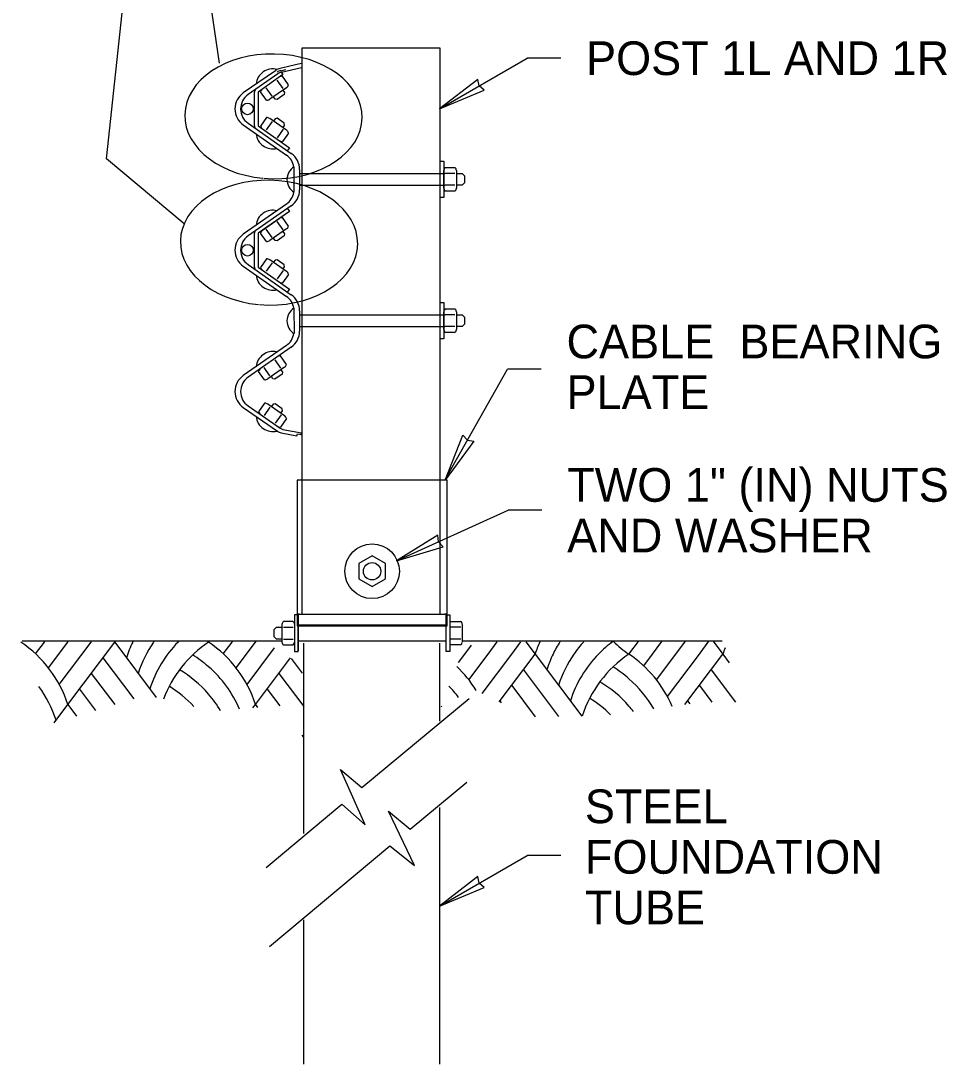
# Model space of a CAD drawing. Extents: x 1312564.2 to 1312581.5, y 1207298.4 to 1207352.6.
# Drawn here: x 1312572.439 to 1312574.64, y 1207329.716 to 1207332.195 of the extents above; entities that cross this region are included whole.
import ezdxf

# ---------------------------------------------------------------- set-up
doc = ezdxf.new("R2010")
doc.units = 0
for name, color, linetype in [('Level 15', 7, 'Continuous'), ('Level 16', 7, 'Continuous'), ('Level 20', 7, 'Continuous'), ('Level 3', 7, 'Continuous'), ('Level 6', 7, 'Continuous')]:
    doc.layers.add(name, color=color, linetype=linetype)

msp = doc.modelspace()

# ---------------------------------------------------------------- linework, layer by layer
at = {"layer": 'Level 15'}
for p, q in [((1312572.9113, 1207332.094), (1312572.7708, 1207333.0638)), ((1312573.4336, 1207331.9858), (1312573.6419, 1207332.1061)), ((1312573.722, 1207332.1061), (1312573.6419, 1207332.1061)), ((1312573.4469, 1207331.1033), (1312573.5956, 1207331.3671)), ((1312573.6757, 1207331.3671), (1312573.5956, 1207331.3671)), ((1312573.3321, 1207330.9118), (1312573.5972, 1207331.032)), ((1312573.6773, 1207331.032), (1312573.5972, 1207331.032)), ((1312573.4336, 1207330.0915), (1312573.6419, 1207330.2118)), ((1312573.722, 1207330.2118), (1312573.6419, 1207330.2118))]:
    msp.add_line(p, q, dxfattribs=at)
for points in [[(1312572.8272, 1207331.7124), (1312572.6428, 1207331.8673), (1312572.7708, 1207333.0638)], [(1312573.0218, 1207330.1827), (1312573.2017, 1207330.3332), (1312573.2574, 1207330.2842), (1312573.1987, 1207330.4157), (1312573.2496, 1207330.3731), (1312573.5046, 1207330.5844)], [(1312573.03, 1207329.9954), (1312573.3162, 1207330.2346), (1312573.3742, 1207330.1882), (1312573.3131, 1207330.3171), (1312573.364, 1207330.2745), (1312573.4986, 1207330.3861)]]:
    msp.add_lwpolyline(points, dxfattribs=at)
for points in [[(1312573.4336, 1207331.9858), (1312573.54, 1207332.03), (1312573.528, 1207332.0403), (1312573.5251, 1207332.0559)], [(1312573.4474, 1207331.1033), (1312573.4896, 1207331.2105), (1312573.5001, 1207331.1987), (1312573.5157, 1207331.1961)], [(1312573.3321, 1207330.9118), (1312573.4424, 1207330.9454), (1312573.4314, 1207330.9568), (1312573.43, 1207330.9726)], [(1312573.4336, 1207330.0915), (1312573.54, 1207330.1357), (1312573.528, 1207330.146), (1312573.5251, 1207330.1616)]]:
    msp.add_lwpolyline(points, close=True, dxfattribs=at)
for centre in [(1312573.0394, 1207331.9679), (1312573.0289, 1207331.6678)]:
    msp.add_ellipse(centre, major_axis=(0.2106, -0.004), ratio=0.703427, start_param=4.618435, end_param=10.890865, dxfattribs=at)
at = {"layer": 'Level 16'}
for p, q in [((1312573.0439, 1207332.0765), (1312572.9677, 1207332.0236)), ((1312573.1063, 1207332.0832), (1312573.0585, 1207332.0725)), ((1312573.0501, 1207332.069), (1312572.9791, 1207332.0196)), ((1312572.979, 1207331.9515), (1312573.0818, 1207331.8797)), ((1312572.9677, 1207331.9478), (1312573.0704, 1207331.8761)), ((1312573.0881, 1207331.848), (1312573.0881, 1207331.7875)), ((1312573.1015, 1207331.8419), (1312573.1015, 1207331.7934)), ((1312573.0704, 1207331.7595), (1312572.9677, 1207331.6877)), ((1312573.0818, 1207331.7555), (1312572.979, 1207331.6838)), ((1312572.9677, 1207331.612), (1312573.0704, 1207331.5402)), ((1312572.979, 1207331.6157), (1312573.0818, 1207331.5439)), ((1312573.0878, 1207331.5118), (1312573.0883, 1207331.4518)), ((1312573.1015, 1207331.506), (1312573.1015, 1207331.4576)), ((1312573.0704, 1207331.4237), (1312572.9677, 1207331.3519)), ((1312573.0818, 1207331.4197), (1312572.979, 1207331.348)), ((1312572.9677, 1207331.2761), (1312573.0494, 1207331.2197)), ((1312572.9791, 1207331.2798), (1312573.0553, 1207331.2268)), ((1312573.0621, 1207331.224), (1312573.1058, 1207331.2163)), ((1312573.0968, 1207331.2132), (1312573.105, 1207331.2118)), ((1312573.105, 1207331.2118), (1312573.1058, 1207331.2163))]:
    msp.add_line(p, q, dxfattribs=at)
for points in [[(1312573.1065, 1207332.0934), (1312573.0948, 1207332.0908), (1312573.0521, 1207332.0805)], [(1312573.0576, 1207331.2159), (1312573.0952, 1207331.2088), (1312573.0963, 1207331.2133)]]:
    msp.add_lwpolyline(points, dxfattribs=at)
for centre, radius, start, end in [((1312573.0567, 1207332.0604), 0.0206, 102.8809, 128.457), ((1312573.0624, 1207332.0511), 0.0219, 100, 124.808), ((1312572.9941, 1207331.9857), 0.0462, 124.808, 235.0609), ((1312573.0028, 1207331.9855), 0.0415, 124.808, 235.0609), ((1312573.0553, 1207331.8419), 0.0462, 360, 55.0609), ((1312573.0466, 1207331.842), 0.0415, 8.0857, 55.0609), ((1312573.0466, 1207331.7935), 0.0415, 304.9391, 351.4643), ((1312573.0553, 1207331.7934), 0.0462, 304.9391, 360), ((1312572.9941, 1207331.6499), 0.0462, 124.9391, 235.0609), ((1312573.0028, 1207331.6497), 0.0415, 124.9391, 235.0609), ((1312573.0466, 1207331.5062), 0.0415, 7.8569, 55.0609), ((1312573.0553, 1207331.506), 0.0462, 360, 55.0609), ((1312573.0553, 1207331.4576), 0.0462, 304.9391, 360), ((1312573.0466, 1207331.4577), 0.0415, 304.9391, 352.092), ((1312572.9941, 1207331.314), 0.0462, 124.9391, 235.192), ((1312573.0028, 1207331.3139), 0.0415, 124.9391, 235.192), ((1312573.0621, 1207331.236), 0.0206, 231.543, 257.1191), ((1312573.0651, 1207331.2411), 0.0173, 235.192, 260)]:
    msp.add_arc(centre, radius, start, end, dxfattribs=at)
at = {"layer": 'Level 3'}
for p, q in [((1312573.1067, 1207332.1298), (1312573.1067, 1207330.786)), ((1312573.1107, 1207330.7162), (1312573.1107, 1207330.2635)), ((1312573.4336, 1207330.7162), (1312573.4336, 1207330.5307)), ((1312573.4336, 1207330.3258), (1312573.4336, 1207329.7158)), ((1312573.1107, 1207330.0587), (1312573.1107, 1207329.7158))]:
    msp.add_line(p, q, dxfattribs=at)
msp.add_lwpolyline([(1312573.4355, 1207330.786), (1312573.4355, 1207332.1297), (1312573.1066, 1207332.1297)], dxfattribs=at)
at = {"layer": 'Level 6'}
for p, q in [((1312573.0621, 1207332.0672), (1312573.0028, 1207332.0258)), ((1312573.0622, 1207332.0339), (1312573.0482, 1207332.054)), ((1312573.0586, 1207332.0722), (1312573.0621, 1207332.0672)), ((1312573.0753, 1207332.0431), (1312573.0613, 1207332.0632)), ((1312572.9941, 1207331.9456), (1312572.9941, 1207332.0258)), ((1312573.0028, 1207332.0258), (1312573.0028, 1207331.9456)), ((1312573.0229, 1207332.0064), (1312573.0088, 1207332.0265)), ((1312573.036, 1207332.0156), (1312573.022, 1207332.0357)), ((1312573.0704, 1207332.0361), (1312573.0311, 1207332.0086)), ((1312572.969, 1207331.9749), (1312572.969, 1207331.975)), ((1312573.0229, 1207331.9649), (1312573.0088, 1207331.9448)), ((1312573.036, 1207331.9558), (1312573.022, 1207331.9357)), ((1312573.0704, 1207331.9352), (1312573.0311, 1207331.9627)), ((1312573.0028, 1207331.9456), (1312573.0774, 1207331.8934)), ((1312573.0622, 1207331.9374), (1312573.0482, 1207331.9173)), ((1312573.0753, 1207331.9283), (1312573.0613, 1207331.9082)), ((1312573.0774, 1207331.8934), (1312573.0724, 1207331.8863)), ((1312573.1007, 1207331.8319), (1312573.4469, 1207331.8319)), ((1312573.4443, 1207331.7972), (1312573.4443, 1207331.8392)), ((1312573.4476, 1207331.8462), (1312573.4707, 1207331.8462)), ((1312573.4707, 1207331.8322), (1312573.4476, 1207331.8322)), ((1312573.474, 1207331.8392), (1312573.474, 1207331.7972)), ((1312573.1007, 1207331.8045), (1312573.4469, 1207331.8045)), ((1312573.4707, 1207331.8042), (1312573.4476, 1207331.8042)), ((1312573.4707, 1207331.7902), (1312573.4476, 1207331.7902)), ((1312573.0478, 1207331.7437), (1312572.9981, 1207331.709)), ((1312573.0753, 1207331.7072), (1312573.0613, 1207331.7273)), ((1312573.0138, 1207331.6977), (1312573.0531, 1207331.7251)), ((1312573.0622, 1207331.6981), (1312573.0482, 1207331.7182)), ((1312572.9941, 1207331.6097), (1312572.9941, 1207331.69)), ((1312573.0229, 1207331.6706), (1312573.0088, 1207331.6907)), ((1312573.036, 1207331.6798), (1312573.022, 1207331.6999)), ((1312573.0704, 1207331.7003), (1312573.0311, 1207331.6728)), ((1312572.9904, 1207331.6545), (1312572.9906, 1207331.6548)), ((1312572.9672, 1207331.6408), (1312572.967, 1207331.641)), ((1312572.967, 1207331.641), (1312572.967, 1207331.641)), ((1312573.0229, 1207331.6291), (1312573.0088, 1207331.609)), ((1312573.0028, 1207331.6097), (1312573.0774, 1207331.5576)), ((1312573.036, 1207331.6199), (1312573.022, 1207331.5998)), ((1312573.0704, 1207331.5994), (1312573.0311, 1207331.6269)), ((1312573.0622, 1207331.6016), (1312573.0482, 1207331.5815)), ((1312573.0753, 1207331.5925), (1312573.0613, 1207331.5724)), ((1312573.0774, 1207331.5576), (1312573.0724, 1207331.5505)), ((1312573.4476, 1207331.5104), (1312573.4707, 1207331.5104)), ((1312573.1007, 1207331.4961), (1312573.4469, 1207331.4961)), ((1312573.4443, 1207331.4614), (1312573.4443, 1207331.5034)), ((1312573.4707, 1207331.4964), (1312573.4476, 1207331.4964)), ((1312573.474, 1207331.5034), (1312573.474, 1207331.4614)), ((1312573.1007, 1207331.4687), (1312573.4469, 1207331.4687)), ((1312573.4707, 1207331.4684), (1312573.4476, 1207331.4684)), ((1312573.4707, 1207331.4544), (1312573.4476, 1207331.4544)), ((1312573.0572, 1207331.3694), (1312573.0432, 1207331.3895)), ((1312573.0703, 1207331.3785), (1312573.0563, 1207331.3986)), ((1312573.0179, 1207331.3419), (1312573.0039, 1207331.362)), ((1312573.031, 1207331.351), (1312573.017, 1207331.3711)), ((1312573.0654, 1207331.3716), (1312573.0261, 1207331.3441)), ((1312573.0181, 1207331.2863), (1312573.004, 1207331.2662)), ((1312573.0656, 1207331.2566), (1312573.0263, 1207331.2841)), ((1312573.0312, 1207331.2771), (1312573.0171, 1207331.257)), ((1312573.0574, 1207331.2588), (1312573.0433, 1207331.2387)), ((1312573.0705, 1207331.2496), (1312573.0564, 1207331.2295)), ((1312573.0597, 1207330.7608), (1312573.0597, 1207330.7188)), ((1312573.0861, 1207330.7678), (1312573.063, 1207330.7678)), ((1312573.1007, 1207330.7848), (1312573.4469, 1207330.7848)), ((1312573.4581, 1207330.7678), (1312573.4845, 1207330.7678)), ((1312573.4878, 1207330.7608), (1312573.4878, 1207330.7188)), ((1312573.063, 1207330.7538), (1312573.0861, 1207330.7538)), ((1312573.4495, 1207330.7588), (1312573.0981, 1207330.7588)), ((1312573.4845, 1207330.7538), (1312573.4581, 1207330.7538)), ((1312572.4424, 1207330.7213), (1312573.0581, 1207330.7213)), ((1312572.4743, 1207330.691), (1312572.4951, 1207330.7187)), ((1312572.4951, 1207330.7187), (1312572.4952, 1207330.7189)), ((1312572.5049, 1207330.6575), (1312572.5508, 1207330.7187)), ((1312572.5307, 1207330.6176), (1312572.6065, 1207330.7187)), ((1312572.5508, 1207330.7187), (1312572.5511, 1207330.7191)), ((1312572.5508, 1207330.5701), (1312572.6623, 1207330.7187)), ((1312572.6065, 1207330.7187), (1312572.607, 1207330.7194)), ((1312572.6617, 1207330.7196), (1312572.6623, 1207330.7187)), ((1312572.6623, 1207330.7187), (1312572.761, 1207330.5871)), ((1312572.8852, 1207330.7187), (1312572.8865, 1207330.7204)), ((1312572.9202, 1207330.691), (1312572.941, 1207330.7187)), ((1312572.941, 1207330.7187), (1312572.9424, 1207330.7206)), ((1312572.9508, 1207330.6575), (1312572.9967, 1207330.7187)), ((1312572.9967, 1207330.7187), (1312572.9983, 1207330.7208)), ((1312573.063, 1207330.7258), (1312573.0861, 1207330.7258)), ((1312573.063, 1207330.7118), (1312573.0861, 1207330.7118)), ((1312573.4495, 1207330.7208), (1312573.0981, 1207330.7208)), ((1312573.4845, 1207330.7258), (1312573.4581, 1207330.7258)), ((1312573.4845, 1207330.7118), (1312573.4581, 1207330.7118)), ((1312573.4889, 1207330.7213), (1312574.1055, 1207330.7213)), ((1312573.4939, 1207330.6902), (1312573.5098, 1207330.7113)), ((1312573.5496, 1207330.6902), (1312573.5712, 1207330.7189)), ((1312573.6054, 1207330.6902), (1312573.6271, 1207330.7191)), ((1312573.6394, 1207330.7191), (1312573.6611, 1207330.6902)), ((1312573.8841, 1207330.6902), (1312573.9065, 1207330.7201)), ((1312573.9398, 1207330.6902), (1312573.9624, 1207330.7204)), ((1312573.9955, 1207330.6902), (1312574.0183, 1207330.7206)), ((1312574.0513, 1207330.6902), (1312574.0742, 1207330.7208)), ((1312574.084, 1207330.7208), (1312574.107, 1207330.6902)), ((1312572.9766, 1207330.6176), (1312573.042, 1207330.7048)), ((1312573.4789, 1207330.6702), (1312573.4939, 1207330.6902)), ((1312573.5037, 1207330.6289), (1312573.5496, 1207330.6902)), ((1312573.5353, 1207330.5968), (1312573.6054, 1207330.6902)), ((1312573.576, 1207330.5767), (1312573.6611, 1207330.6902)), ((1312573.6611, 1207330.6902), (1312573.7719, 1207330.5425)), ((1312573.919, 1207330.6624), (1312573.9398, 1207330.6902)), ((1312573.9496, 1207330.6289), (1312573.9955, 1207330.6902)), ((1312573.9755, 1207330.5891), (1312574.0513, 1207330.6902)), ((1312574.0169, 1207330.57), (1312574.107, 1207330.6902)), ((1312574.107, 1207330.6902), (1312574.1225, 1207330.6695)), ((1312572.6344, 1207330.6816), (1312572.7078, 1207330.5837)), ((1312572.9967, 1207330.5701), (1312573.0798, 1207330.6809)), ((1312573.0817, 1207330.6797), (1312573.1077, 1207330.6451)), ((1312572.6065, 1207330.6444), (1312572.6623, 1207330.5701)), ((1312573.0524, 1207330.6444), (1312573.1117, 1207330.5653)), ((1312573.6333, 1207330.653), (1312573.7167, 1207330.5418)), ((1312574.0792, 1207330.653), (1312574.1369, 1207330.576)), ((1312573.6054, 1207330.6159), (1312573.6615, 1207330.5411)), ((1312574.0513, 1207330.6159), (1312574.0812, 1207330.576)), ((1312572.5787, 1207330.6072), (1312572.6168, 1207330.5564)), ((1312573.0246, 1207330.6072), (1312573.0543, 1207330.5676)), ((1312572.5184, 1207330.5269), (1312572.5508, 1207330.5701)), ((1312572.5508, 1207330.5701), (1312572.5713, 1207330.5428)), ((1312572.9908, 1207330.5621), (1312572.9967, 1207330.5701)), ((1312572.9967, 1207330.5701), (1312573.0019, 1207330.5631)), ((1312573.5775, 1207330.5787), (1312573.5807, 1207330.5744)), ((1312574.0234, 1207330.5787), (1312574.0288, 1207330.5716)), ((1312573.1068, 1207330.4976), (1312573.1099, 1207330.4934))]:
    msp.add_line(p, q, dxfattribs=at)
for points in [[(1312573.0567, 1207332.0765), (1312573.0691, 1207332.0795)], [(1312573.0621, 1207332.0303), (1312573.066, 1207332.0248), (1312573.0651, 1207332.02), (1312573.0481, 1207332.0081), (1312573.0433, 1207332.0089), (1312573.0394, 1207332.0144)], [(1312573.0621, 1207331.941), (1312573.066, 1207331.9465), (1312573.0651, 1207331.9514), (1312573.0481, 1207331.9633), (1312573.0433, 1207331.9624), (1312573.0394, 1207331.9569)], [(1312573.474, 1207331.8319), (1312573.4875, 1207331.8319), (1312573.493, 1207331.8265), (1312573.493, 1207331.81), (1312573.4875, 1207331.8045), (1312573.474, 1207331.8045)], [(1312573.0727, 1207331.7488), (1312573.0774, 1207331.7421), (1312573.0028, 1207331.69), (1312573.0028, 1207331.6097)], [(1312573.0621, 1207331.6945), (1312573.066, 1207331.689), (1312573.0651, 1207331.6842), (1312573.0481, 1207331.6723), (1312573.0433, 1207331.6731), (1312573.0394, 1207331.6786)], [(1312573.0621, 1207331.6052), (1312573.066, 1207331.6107), (1312573.0651, 1207331.6155), (1312573.0481, 1207331.6274), (1312573.0433, 1207331.6266), (1312573.0394, 1207331.6211)], [(1312573.474, 1207331.4961), (1312573.4875, 1207331.4961), (1312573.493, 1207331.4906), (1312573.493, 1207331.4742), (1312573.4875, 1207331.4687), (1312573.474, 1207331.4687)], [(1312573.0571, 1207331.3658), (1312573.061, 1207331.3603), (1312573.0601, 1207331.3554), (1312573.0431, 1207331.3435), (1312573.0383, 1207331.3444), (1312573.0344, 1207331.3499)], [(1312573.0573, 1207331.2624), (1312573.0611, 1207331.2679), (1312573.0603, 1207331.2727), (1312573.0432, 1207331.2846), (1312573.0384, 1207331.2838), (1312573.0346, 1207331.2783)], [(1312573.1007, 1207330.7848), (1312573.0981, 1207330.7848), (1312573.0981, 1207330.6983)], [(1312573.4495, 1207330.6983), (1312573.4495, 1207330.7848), (1312573.4469, 1207330.7848)], [(1312573.0597, 1207330.7535), (1312573.0462, 1207330.7535), (1312573.0407, 1207330.748), (1312573.0407, 1207330.7316), (1312573.0462, 1207330.7261), (1312573.0597, 1207330.7261)]]:
    msp.add_lwpolyline(points, dxfattribs=at)
for points in [[(1312573.4356, 1207331.8615), (1312573.4443, 1207331.8615), (1312573.4443, 1207331.7749), (1312573.4356, 1207331.7749)], [(1312573.4356, 1207331.5257), (1312573.4443, 1207331.5257), (1312573.4443, 1207331.4391), (1312573.4356, 1207331.4391)], [(1312573.4519, 1207330.7571), (1312573.4519, 1207331.1033), (1312573.0957, 1207331.1033), (1312573.0957, 1207330.7571)], [(1312573.3053, 1207330.9051), (1312573.2738, 1207330.9234), (1312573.2422, 1207330.9051), (1312573.2422, 1207330.8687), (1312573.2738, 1207330.8505), (1312573.3053, 1207330.8687)], [(1312573.0981, 1207330.7831), (1312573.0894, 1207330.7831), (1312573.0894, 1207330.6965), (1312573.0981, 1207330.6965)], [(1312573.4495, 1207330.7831), (1312573.4581, 1207330.7831), (1312573.4581, 1207330.6965), (1312573.4495, 1207330.6965)]]:
    msp.add_lwpolyline(points, close=True, dxfattribs=at)
for centre, radius in [((1312572.9777, 1207331.9857), 0.0138), ((1312572.9777, 1207331.6499), 0.0138), ((1312573.2738, 1207330.8869), 0.0649), ((1312573.2738, 1207330.8869), 0.0206)]:
    msp.add_circle(centre, radius, dxfattribs=at)
for centre, radius, start, end in [((1312573.038, 1207332.0406), 0.0401, 75.8048, 174.0735), ((1312573.0605, 1207332.055), 0.0219, 100, 124.808), ((1312573.0602, 1207332.0507), 0.0125, 85.2558, 117.7402), ((1312573.0028, 1207332.0258), 0.00865, 141.8048, 180), ((1312573.0209, 1207332.0232), 0.0125, 125.6308, 164.6225), ((1312573.0633, 1207332.0464), 0.0125, 304.9389, 344.6225), ((1312573.0239, 1207332.0189), 0.0125, 265.2558, 304.9399), ((1312573.0239, 1207331.9524), 0.0125, 59.635, 94.7442), ((1312573.0028, 1207331.9456), 0.00865, 180, 235.0609), ((1312573.038, 1207331.9307), 0.0401, 185.9265, 284.1952), ((1312573.0209, 1207331.9481), 0.0125, 195.3775, 223.6443), ((1312573.0633, 1207331.925), 0.0125, 15.3775, 52.592), ((1312573.0602, 1207331.9207), 0.0125, 242.5421, 274.7442), ((1312573.1076, 1207331.8178), 0.036, 122.7791, 237.2209), ((1312573.4534, 1207331.8392), 0.00909, 129.5978, 174.7119), ((1312573.4649, 1207331.8392), 0.00909, 359.9988, 50.4022), ((1312573.4534, 1207331.7972), 0.00909, 185.3057, 230.4022), ((1312573.4649, 1207331.7972), 0.00909, 309.5978, 359.9988), ((1312573.038, 1207331.7049), 0.0401, 75.8048, 174.0735), ((1312573.0602, 1207331.7149), 0.0125, 85.2558, 120.5386), ((1312573.0633, 1207331.7106), 0.0125, 304.9388, 344.6225), ((1312573.0028, 1207331.69), 0.00865, 124.9391, 180), ((1312573.0209, 1207331.6874), 0.0125, 123.5044, 164.6225), ((1312573.0239, 1207331.6831), 0.0125, 265.2558, 304.9399), ((1312573.0239, 1207331.6166), 0.0125, 55.0051, 94.7442), ((1312573.0028, 1207331.6097), 0.00865, 180, 235.0609), ((1312573.0209, 1207331.6123), 0.0125, 195.3775, 229.9696), ((1312573.038, 1207331.5949), 0.0401, 185.9265, 284.1952), ((1312573.0633, 1207331.5892), 0.0125, 15.3775, 56.4343), ((1312573.0602, 1207331.5848), 0.0125, 238.4249, 274.7442), ((1312573.1076, 1207331.482), 0.036, 122.7791, 237.2209), ((1312573.4534, 1207331.5034), 0.00909, 129.5978, 168.0747), ((1312573.4649, 1207331.5034), 0.00909, 359.9988, 50.4022), ((1312573.4534, 1207331.4614), 0.00909, 184.624, 230.4022), ((1312573.4649, 1207331.4614), 0.00909, 309.5978, 359.9988), ((1312573.038, 1207331.369), 0.0401, 77.0788, 174.0735), ((1312573.0553, 1207331.3861), 0.0125, 85.2558, 116.0549), ((1312573.0159, 1207331.3587), 0.0125, 134.8293, 164.6225), ((1312573.0583, 1207331.3818), 0.0125, 309.8302, 344.6225), ((1312573.0189, 1207331.3544), 0.0125, 265.2558, 306.8266), ((1312573.0191, 1207331.2738), 0.0125, 55.0603, 94.7442), ((1312573.0161, 1207331.2695), 0.0125, 195.3775, 224.0218), ((1312573.0584, 1207331.2463), 0.0125, 15.3775, 55.0613), ((1312573.038, 1207331.259), 0.0401, 185.9265, 284.1952), ((1312573.0554, 1207331.242), 0.0125, 241.2922, 274.7442), ((1312573.0688, 1207330.7608), 0.00909, 129.5978, 180.0011), ((1312573.0803, 1207330.7608), 0.00909, 1.7641, 50.4022), ((1312573.4787, 1207330.7608), 0.00909, 3.1624, 50.4022), ((1312572.282, 1207330.4846), 0.2821, 17.6434, 56.0951), ((1312572.9311, 1207330.6332), 0.2821, 162.1756, 162.3566), ((1312572.959, 1207330.5961), 0.2821, 154.2265, 162.3566), ((1312572.959, 1207330.5961), 0.2821, 153.9982, 154.2266), ((1312572.9869, 1207330.5589), 0.2821, 145.491, 162.3566), ((1312573.0147, 1207330.5217), 0.2821, 135.7127, 162.3566), ((1312572.9869, 1207330.5589), 0.2821, 145.1946, 145.4911), ((1312573.0426, 1207330.4846), 0.2821, 123.9036, 159.5831), ((1312573.0147, 1207330.5217), 0.2821, 135.307, 135.7128), ((1312573.0426, 1207330.9529), 0.2821, 235.4873, 236.0964), ((1312572.7279, 1207330.4846), 0.2821, 17.6434, 56.0963), ((1312573.0688, 1207330.7188), 0.00909, 180.0012, 230.4022), ((1312573.0803, 1207330.7188), 0.00909, 309.5978, 349.7194), ((1312573.4787, 1207330.7188), 0.00909, 309.5978, 353.2515), ((1312573.93, 1207330.6047), 0.2821, 156.0387, 162.3566), ((1312573.9578, 1207330.5675), 0.2821, 147.4189, 154.2266), ((1312573.9857, 1207330.5304), 0.2821, 137.8572, 145.4911), ((1312574.0136, 1207330.4932), 0.2821, 126.5208, 135.7128), ((1312574.0414, 1207330.9243), 0.2821, 226.4334, 236.0964), ((1312572.7, 1207330.4474), 0.2821, 48.9597, 58.5465), ((1312573.9578, 1207330.5675), 0.2821, 154.2265, 162.3566), ((1312573.9857, 1207330.5304), 0.2821, 145.491, 162.3566), ((1312574.0136, 1207330.4932), 0.2821, 135.7127, 162.3566), ((1312574.0414, 1207330.456), 0.2821, 123.9036, 162.15), ((1312573.7267, 1207330.456), 0.2821, 22.915, 56.0963), ((1312574.3759, 1207330.6047), 0.2821, 159.1319, 162.3566), ((1312572.6721, 1207330.4103), 0.2821, 40.9413, 59.3021), ((1312572.7, 1207330.4474), 0.2821, 23.3896, 48.9597), ((1312573.2808, 1207330.456), 0.2821, 31.5696, 46.4789), ((1312573.6989, 1207330.4189), 0.2821, 48.9597, 58.5465), ((1312572.2541, 1207330.4474), 0.2821, 17.6434, 35.988), ((1312572.6443, 1207330.3731), 0.2821, 43.1055, 58.4874), ((1312573.2529, 1207330.4189), 0.2821, 36.5842, 43.8132), ((1312573.671, 1207330.3817), 0.2821, 40.9413, 59.3021), ((1312573.6988, 1207330.4189), 0.2821, 30.0182, 48.9597), ((1312572.6721, 1207330.4103), 0.2821, 30.9962, 40.9414), ((1312573.2251, 1207330.3817), 0.2821, 40.9413, 41.0916), ((1312573.2251, 1207330.3817), 0.2821, 40.4867, 40.9414), ((1312573.6431, 1207330.3446), 0.2821, 45.6063, 58.4874), ((1312573.671, 1207330.3817), 0.2821, 37.5056, 40.9414)]:
    msp.add_arc(centre, radius, start, end, dxfattribs=at)

# ---------------------------------------------------------------- texts
at = {"layer": 'Level 20'}
for s, height, p in [('POST 1L AND 1R', 0.080077, (1312573.782, 1207332.0661)), ('CABLE  BEARING ', 0.080077, (1312573.7357, 1207331.3929)), ('PLATE', 0.08008, (1312573.7357, 1207331.2728)), ('TWO 1" (IN) NUTS', 0.080077, (1312573.7373, 1207331.0521)), ('AND WASHER', 0.08008, (1312573.7373, 1207330.9319)), ('STEEL ', 0.08008, (1312573.7793, 1207330.2884)), ('FOUNDATION', 0.08008, (1312573.7793, 1207330.1683)), ('TUBE', 0.08008, (1312573.7793, 1207330.0481))]:
    msp.add_text(s, height=height, dxfattribs=at).set_placement(p)

doc.saveas('drawing.dxf')
